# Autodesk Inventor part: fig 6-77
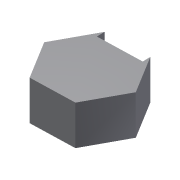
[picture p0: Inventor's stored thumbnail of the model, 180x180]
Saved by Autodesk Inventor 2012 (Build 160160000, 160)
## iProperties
Created: 2009-03
Part Number: fig 6-77
Document SubType Name: Modeling
Designer: Sham
Density: 1 g/cm^3
Material: Default
Author: Sham
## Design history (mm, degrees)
sketch "Sketch5"
  geometry: L1 (-5.929, 9.627)-(5.372, 9.948); L2 (5.372, 9.948)-(11.301, 0.321); L3 (11.301, 0.321)-(5.929, -9.627); L4 (5.929, -9.627)-(-5.372, -9.948); L5 (-5.372, -9.948)-(-11.301, -0.321); L6 (-11.301, -0.321)-(-5.929, 9.627); 1 further point
  constraints: 12 end point, 13 other
extrude "Extrusion3" new body sketch "Sketch5" distance "d13" = 10; taper "d14" = 0 deg
thicken "Thicken2" dims "d15" = 2, "d16" = 2
body "Solid4"
